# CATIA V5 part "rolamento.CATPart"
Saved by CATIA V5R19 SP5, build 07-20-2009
Part number: rolamento
Bounding box of the stored display mesh (mm): x 0 to 8, y -13 to 13, z -12.803 to 12.803
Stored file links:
  Z:\UA\ATLAS\atlascar\ServoPiloto\dir\suportePotenciometro\V2\rolamento.CATPart
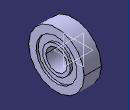
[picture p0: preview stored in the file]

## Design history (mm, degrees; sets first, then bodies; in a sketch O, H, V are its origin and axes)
Body1 (main body)
  Sketch1 on yz-plane, origin (0, 0, 0), H (0, 1, 0), V (0, 0, 1)
    circle A1 centre (0, 0) radius 5
    circle A2 centre (0, 0) radius 13
    radius A1 = 5
    radius A2 = 13
  Pad1: profile Sketch1, direction (1, 0, 0), length 8
  Sketch2 on zx-plane, origin (0, 0, 0), H (-1, 0, 0), V (0, 0, 1)
    line L1 (-1, 9.5424) -> (1.1929, 9.5424)
    line L2 (1.1929, 9.5424) -> (1.1929, 6.5)
    line L3 (1.1929, 6.5) -> (-1, 6.5)
    line L4 (-1, 6.5) -> (-1, 9.5424)
    point P5 (-10.8519, 9.5424)
    line L5 (-10.8519, 9.5424) -> (-7, 9.5424)
    line L6 (-7, 9.5424) -> (-7, 6.5)
    line L7 (-7, 6.5) -> (-10.8519, 6.5)
    line L8 (-10.8519, 6.5) -> (-10.8519, 9.5424)
    point P7 (-7, 6.5)
    distance L6 L4 = 6
    distance V L4 = 1
    distance L3 H = 6.5
    horizontal: L1 H, L3 H, L5 H, L7 H
    vertical: L2 V, L4 V, L6 V, L8 V
    coincidence: P5 L1, P7 L3
  Groove1: profile Sketch2, axis axis of face of Pad1 from Sketch1.A1, angle 360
